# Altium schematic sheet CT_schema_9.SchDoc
size 274 x 160 mm
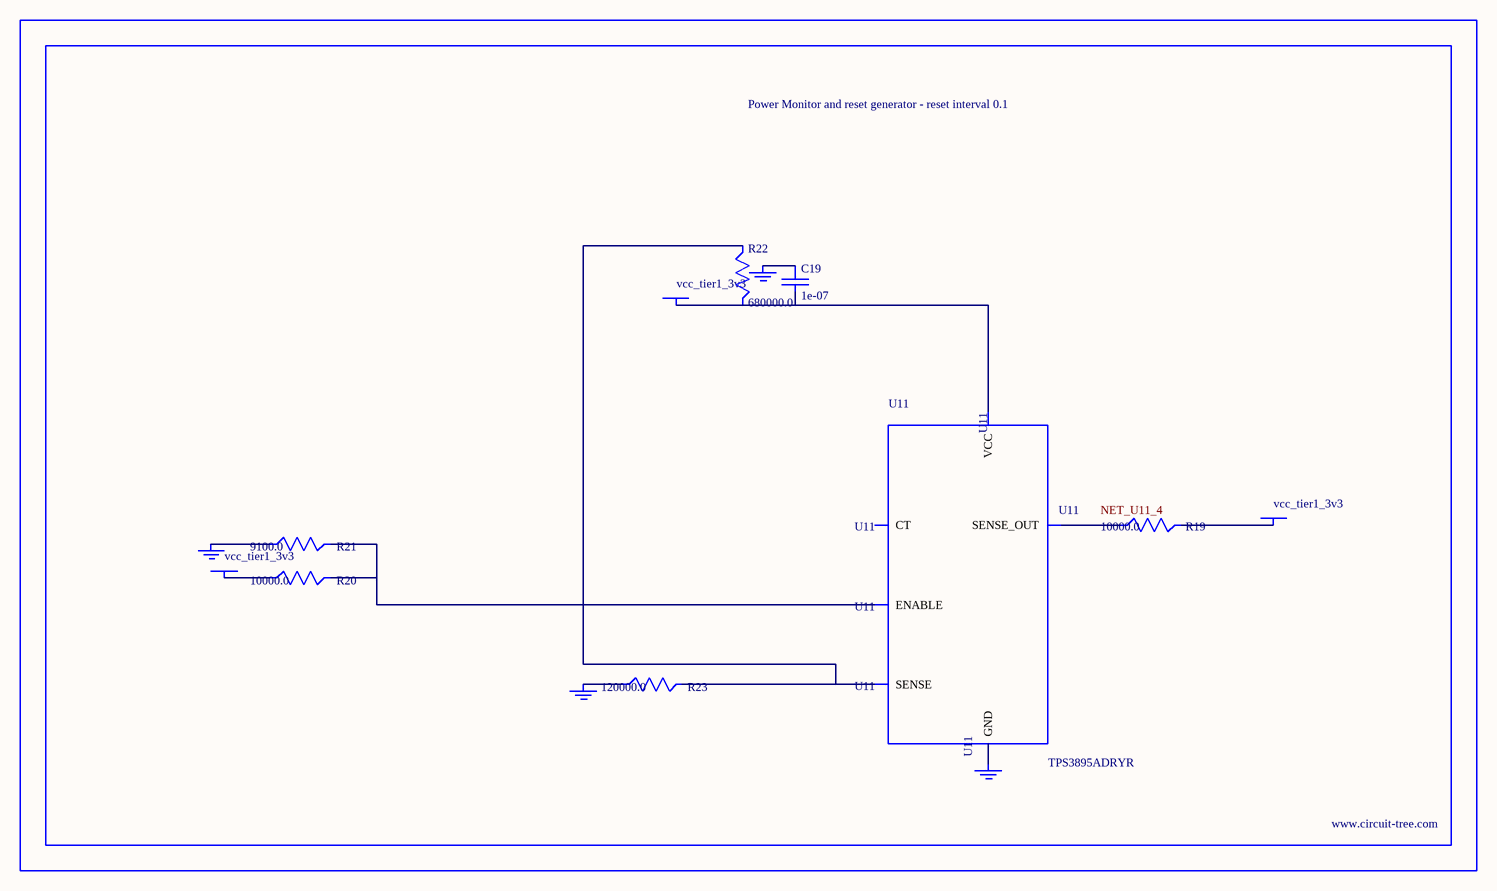
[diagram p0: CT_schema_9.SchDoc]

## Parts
BORDER8  (no value)
C19  1e-07  [C0402]
GND_INSTANCE_8_0  (no value)
GND_INSTANCE_8_1  (no value)
GND_INSTANCE_8_2  (no value)
GND_INSTANCE_8_3  (no value)
POWER_INSTANCE_8_0  vcc_tier1_3v3
POWER_INSTANCE_8_1  vcc_tier1_3v3
POWER_INSTANCE_8_2  vcc_tier1_3v3
R19  10000.0  [R0603]
R20  10000.0  [R0603]
R21  9100.0  [R0603]
R22  680000.0  [R0603]
R23  120000.0  [R0603]
U11  TPS3895ADRYR  [SON-6]

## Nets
NetC19_1: C19.1 GND_INSTANCE_8_2.0(GND)
NetC19_2: C19.2 POWER_INSTANCE_8_2.0(PWR) R22.2 U11.6(VCC)
NetGND_INSTANCE_8_0_0: GND_INSTANCE_8_0.0(GND) R21.1
NetGND_INSTANCE_8_1_0: GND_INSTANCE_8_1.0(GND) R23.1
NetGND_INSTANCE_8_3_0: GND_INSTANCE_8_3.0(GND) U11.2(GND)
NetPOWER_INSTANCE_8_0_0: POWER_INSTANCE_8_0.0(PWR) R20.1
NetPOWER_INSTANCE_8_1_0: POWER_INSTANCE_8_1.0(PWR) R19.2
NetR19_1: R19.1 U11.4(SENSE_OUT)
NetR20_2: R20.2 R21.2 U11.1(ENABLE)
NetR22_1: R22.1 R23.2 U11.3(SENSE)

Not connected (* = marked no-connect by the designer): U11 5(CT)

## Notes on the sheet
- Labels drawn without touching a wire or pin: NET_U11_4

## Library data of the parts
BORDER8 = BORDER_PAGE8
C19 = C0402C104K3RACTU
GND_INSTANCE_8_0-GND_INSTANCE_8_3 = GND
POWER_INSTANCE_8_0-POWER_INSTANCE_8_2 = PWR
R19 R20 = RC0603JR-0710KL
R21 = RC0603JR-079K1L
R22 = RC0603JR-07680KL
R23 = RC0603JR-07120KL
